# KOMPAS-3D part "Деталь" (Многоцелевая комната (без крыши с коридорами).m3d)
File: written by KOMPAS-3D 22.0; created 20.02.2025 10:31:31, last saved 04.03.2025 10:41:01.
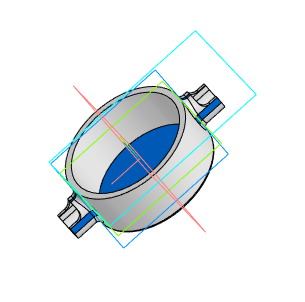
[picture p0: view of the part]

Document properties: Автор: Пользователь Windows; Полное имя файла: C:\Users\Student\Documents\Картошечка\База Сабнатика\Многоцелевая комната\Многоцелевая комната (без крыши с коридорами).m3d

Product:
- Part/product: Деталь
    Масса: 0.116811

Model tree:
1. Эскиз:3
2. Элемент вращения:1
     Угол 1 = 360
3. Скругление:1  (with: Элемент вращения:1)
     Радиус = 1
4. Эскиз:4  (with: Элемент вращения:1)
5. Элемент выдавливания:1
     Расстояние 2 = 6.1
6. Эскиз:5  (with: Элемент выдавливания:1)
7. Элемент выдавливания:2
     Расстояние 2 = 19
8. Смещенная плоскость:1
     Расстояние = 25
9. Эскиз:6
10. Элемент выдавливания:3
     Расстояние 1 = 10; Расстояние 2 = 4
11. Элемент выдавливания:4  (with: Элемент выдавливания:2)
     Расстояние 1 = 22
12. Эскиз:7
13. Элемент выдавливания:5
     Расстояние 2 = 10
14. Скругление:2  (with: Элемент выдавливания:3)
     Радиус = 2
15. Смещенная плоскость:2
     Расстояние = 7
16. Эскиз:8  (with: Элемент выдавливания:3)
17. Элемент выдавливания:6
     Расстояние 2 = 5.5
18. Скругление:3  (with: Элемент выдавливания:6)
     Радиус = 3
19. Зеркальный массив:1
20. Экземпляр ( 1 )
21. Экземпляр ( 2 )  (with: Элемент выдавливания:6, Скругление:3, Элемент выдавливания:3, Скругление:2)
22. Элемент выдавливания:7  (with: Элемент выдавливания:2)
     Расстояние 1 = 21
23. Элемент выдавливания:8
